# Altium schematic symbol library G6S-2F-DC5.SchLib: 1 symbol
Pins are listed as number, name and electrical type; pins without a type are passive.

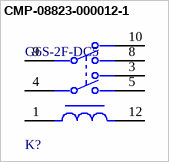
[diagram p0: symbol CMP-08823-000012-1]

## CMP-08823-000012-1
designator K?, comment G6S-2F-DC5
RELAY TELECOM DPDT 2A 5VDC; Manufacturer: Omron; Coil Resistance: 178Ω; Coil Current: 28.1mA; Coil Voltage: 5V; Standoff Height: 0.35mm; Coil Power: 140mW; Coil Type: Non-Latching; Number Of Contacts: 2
footprint FP-G6S-2F-DC5-MFG
pins: 1, 3, 4, 5, 8, 9, 10, 12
